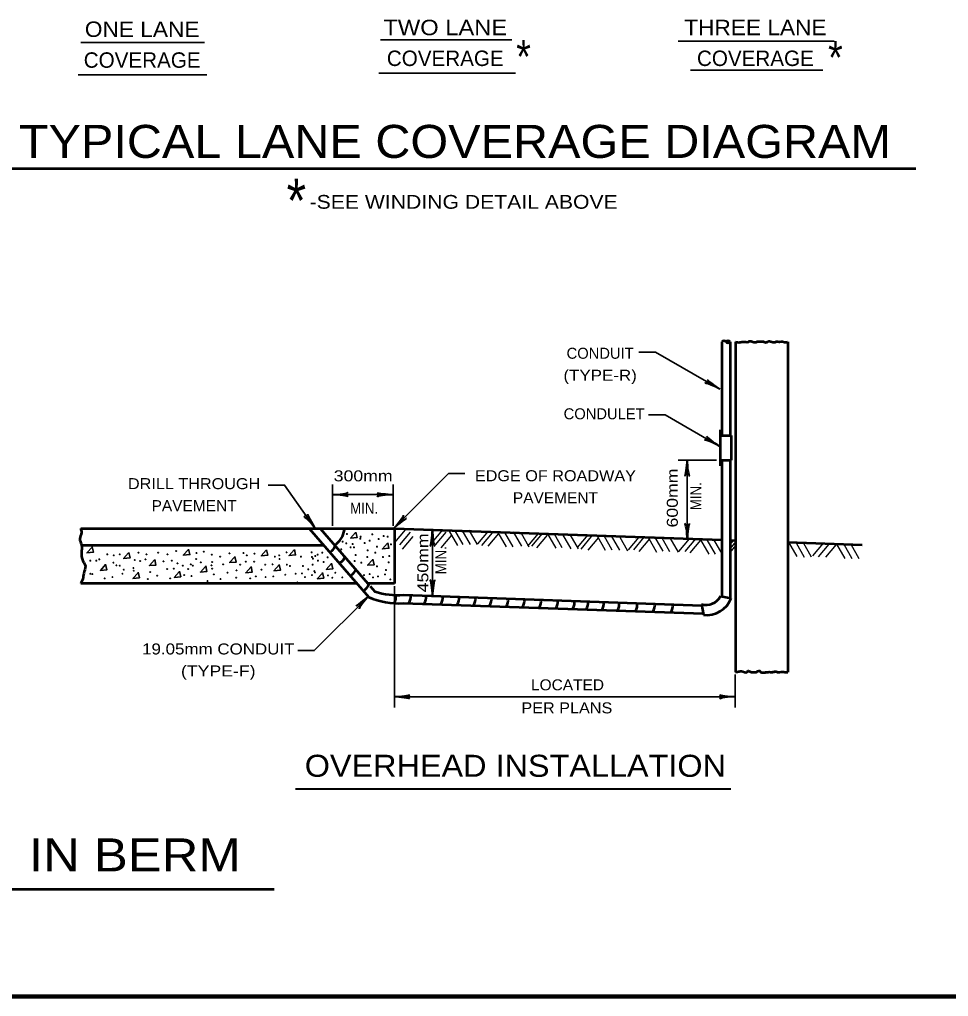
# Model space of a CAD drawing. Extents: x -90 to 623, y -379 to 75.
# Drawn here: x 208.1 to 376.8, y -369 to -191.5 of the extents above; entities that cross this region are included whole.
import ezdxf
from ezdxf.enums import TextEntityAlignment as Align

# ---------------------------------------------------------------- set-up
doc = ezdxf.new("R2010")
doc.units = 0
doc.header["$LTSCALE"] = 0.8
doc.layers.add('1', color=7, linetype='Continuous', lineweight=35)

msp = doc.modelspace()

# ---------------------------------------------------------------- linework, layer by layer
at = {"layer": '1'}
for p, q in [((273.6443, -195.1968), (297.5145, -195.1968)), ((219.2203, -195.6742), (241.6589, -195.6742)), ((327.7501, -195.4353), (356.0764, -195.4353)), ((218.7429, -201.5622), (242.1358, -201.5622)), ((273.3261, -201.2439), (298.1557, -201.2439)), ((329.9779, -200.6867), (354.0093, -200.6867)), ((334.7117, -271.5813), (327.7117, -271.5813)), ((329.3632, -271.5813), (329.3632, -285.9298)), ((264.9297, -283.5143), (264.9297, -276.0143)), ((275.9297, -283.5143), (275.9297, -276.0143)), ((264.9297, -277.8252), (275.9297, -277.8252)), ((283.0888, -284.2984), (283.0888, -296.1737)), ((276.1878, -294.4728), (276.1878, -316.4728)), ((338.0836, -310.4742), (338.0836, -316.4728)), ((276.1108, -314.5437), (338.084, -314.5437))]:
    msp.add_line(p, q, dxfattribs=at)
at = {"layer": '1', "lineweight": 53}
for p, q in [((204.4208, -218.5891), (370.8755, -218.5891)), ((335.6542, -250.0603), (335.6542, -267.0735)), ((337.1542, -250.0603), (337.1542, -267.0444)), ((338.1542, -250.0603), (338.1542, -310.0603)), ((347.6542, -250.0603), (347.6542, -310.0603)), ((335.3657, -266.0735), (335.3657, -272.5735)), ((335.3657, -267.0735), (337.3657, -267.0735)), ((337.3657, -267.0735), (337.3657, -271.5735)), ((335.3657, -271.5735), (336.1215, -271.5735)), ((335.6542, -271.6081), (335.6542, -296.3446)), ((260.7029, -283.9838), (271.5212, -296.4288)), ((262.6904, -283.9838), (271.3629, -293.9603)), ((276.1904, -283.9838), (335.6577, -286.0605)), ((219.1904, -286.9838), (263.3107, -286.9838)), ((337.1684, -286.1132), (338.1427, -286.1472)), ((347.6183, -286.4781), (361.1402, -286.9502)), ((269.264, -293.9838), (219.1904, -293.9838)), ((276.1904, -293.9838), (271.3599, -293.9838)), ((271.8045, -294.4684), (272.6533, -295.4447)), ((277.8081, -296.0476), (332.0119, -297.9405)), ((335.4013, -296.3), (337.3707, -296.6472)), ((277.7557, -297.5467), (332.2782, -299.4507)), ((331.9733, -297.7213), (332.3205, -299.6909)), ((122.0016, -349.4891), (254.329, -349.4891))]:
    msp.add_line(p, q, dxfattribs=at)
at = {"layer": '1', "lineweight": 25}
for p, q in [((278.1212, -284.214), (276.1928, -286.5123)), ((279.0133, -284.6195), (277.085, -286.9178)), ((279.5, -285.4306), (277.5717, -287.7289)), ((284.9343, -284.214), (283.006, -286.5123)), ((285.5021, -284.6195), (283.5738, -286.9178)), ((286.5565, -285.1873), (284.6282, -287.4856)), ((286.1406, -284.4443), (287.6406, -287.0424)), ((287.1139, -284.2821), (288.6139, -286.8802)), ((288.4117, -284.2821), (289.9117, -286.8802)), ((289.7094, -284.2821), (291.2094, -286.8802)), ((293.2074, -284.4573), (291.2791, -286.7557)), ((293.9374, -284.7817), (292.0091, -287.0801)), ((295.0729, -284.8628), (293.1446, -287.1612)), ((294.9815, -284.6877), (296.4815, -287.2858)), ((296.1982, -284.6877), (297.6982, -287.2858)), ((297.7392, -284.6065), (299.2392, -287.2046)), ((299.1181, -284.6877), (300.6181, -287.2858)), ((302.2917, -284.8628), (300.3633, -287.1612)), ((303.0217, -284.8628), (301.0933, -287.1612)), ((303.9138, -285.1873), (301.9855, -287.4856)), ((303.9846, -284.9309), (305.4846, -287.529)), ((305.1202, -284.8498), (306.6202, -287.4479)), ((306.7423, -285.0932), (308.2423, -287.6912)), ((308.0401, -285.0932), (309.5401, -287.6912)), ((311.2947, -285.1062), (309.3664, -287.4045)), ((311.9437, -285.4306), (310.0153, -287.7289)), ((313.2414, -285.5928), (311.3131, -287.8912)), ((312.9878, -285.3365), (314.4878, -287.9346)), ((314.2043, -285.2554), (315.7043, -287.8535)), ((315.5832, -285.3365), (317.0832, -287.9346)), ((317.0432, -285.4176), (318.5432, -288.0157)), ((320.5817, -285.5523), (318.6534, -287.8506)), ((321.5145, -285.5523), (319.5862, -287.8506)), ((322.3152, -285.6609), (323.8152, -288.259)), ((323.4507, -285.4987), (324.9507, -288.0968)), ((324.6674, -285.5798), (326.1674, -288.1779)), ((326.2085, -285.6609), (327.7085, -288.259)), ((322.5283, -285.8362), (320.6, -288.1345)), ((329.7065, -285.8767), (327.7782, -288.175)), ((330.8826, -285.8767), (328.9543, -288.175)), ((331.7748, -286.0795), (329.8465, -288.3778)), ((331.805, -286.0665), (333.305, -288.6646)), ((332.9406, -286.0665), (334.4406, -288.6646)), ((334.1572, -285.9854), (335.6572, -288.5835)), ((337.7128, -286.1322), (337.1542, -286.7982)), ((338.1542, -286.4056), (337.1542, -287.5974)), ((338.1542, -287.0597), (337.1542, -288.2515)), ((347.7923, -286.4734), (349.2923, -289.0715)), ((349.1294, -286.5897), (350.6294, -289.1877)), ((350.4084, -286.5316), (351.9084, -289.1297)), ((354.0408, -286.6608), (352.1125, -288.9592)), ((355.0872, -286.8352), (353.1589, -289.1336)), ((356.4243, -286.8934), (354.496, -289.1918)), ((356.5127, -286.8222), (358.0127, -289.4203)), ((357.7917, -286.8222), (359.2917, -289.4203)), ((359.0707, -286.8222), (360.5707, -289.4203))]:
    msp.add_line(p, q, dxfattribs=at)
at = {"layer": '1', "lineweight": 40}
msp.add_line((258.2395, -331.2874), (337.3024, -331.2874), dxfattribs=at)
at = {"layer": '1', "lineweight": 158}
msp.add_line((617.1938, -368.9978), (-42.4728, -368.9978), dxfattribs=at)
at = {"layer": '1'}
for points in [[(335.2931, -258.6751), (323.6017, -251.9251), (320.6017, -251.9251)], [(335.1887, -269.0025), (325.3458, -263.3197), (322.3458, -263.3197)], [(276.0824, -283.9095), (285.9819, -274.01), (288.9819, -274.01)], [(261.7322, -283.9311), (256.2447, -276.094), (253.2447, -276.094)], [(269.1261, -284.694), (268.2047, -285.7305), (269.3947, -285.6153), (269.1644, -284.6173)], [(221.2519, -287.3774), (220.3306, -288.4139), (221.5206, -288.2987), (221.2902, -287.3007)], [(274.9197, -286.6456), (273.9984, -287.6821), (275.1884, -287.5669), (274.9581, -286.5688)], [(227.8994, -288.4142), (226.9781, -289.4507), (228.1681, -289.3355), (227.9377, -288.3374)], [(238.755, -287.8043), (237.8337, -288.8408), (239.0237, -288.7257), (238.7933, -287.7276)], [(247.1711, -289.146), (246.2498, -290.1825), (247.4398, -290.0673), (247.2094, -289.0693)], [(252.9038, -287.9262), (251.9824, -288.9627), (253.1724, -288.8476), (252.9421, -287.8495)], [(257.9656, -287.8653), (257.0442, -288.9018), (258.2342, -288.7867), (258.0039, -287.7886)], [(223.6914, -290.5487), (222.7701, -291.5852), (223.9601, -291.47), (223.7297, -290.4719)], [(232.5953, -289.6949), (231.674, -290.7314), (232.864, -290.6162), (232.6337, -289.6182)], [(241.8653, -290.8536), (240.9439, -291.8901), (242.1339, -291.7749), (241.9036, -290.7768)], [(250.0984, -290.9756), (249.1771, -292.0121), (250.3671, -291.8969), (250.1367, -290.8988)], [(255.2212, -290.6097), (254.2999, -291.6462), (255.4899, -291.531), (255.2596, -290.5329)], [(264.7351, -290.3657), (263.8137, -291.4022), (265.0037, -291.2871), (264.7734, -290.289)], [(272.2363, -289.6339), (271.315, -290.6704), (272.505, -290.5553), (272.2747, -289.5572)], [(229.607, -292.0123), (228.6857, -293.0488), (229.8757, -292.9337), (229.6453, -291.9356)], [(237.1083, -291.8294), (236.187, -292.8659), (237.377, -292.7507), (237.1467, -291.7527)], [(263.0884, -292.0733), (262.1671, -293.1098), (263.3571, -292.9947), (263.1268, -291.9966)], [(271.5311, -296.2456), (261.6316, -306.1451), (258.6316, -306.1451)]]:
    msp.add_lwpolyline(points, dxfattribs=at)
at = {"layer": '1', "lineweight": 53}
for points in [[(336.1215, -271.5735), (337.1098, -271.5735), (337.3657, -271.5735)], [(337.1542, -271.6081), (337.1542, -286.1272), (337.1542, -296.6091)], [(219.1904, -283.9838), (276.1904, -283.9838), (276.1904, -293.9838)]]:
    msp.add_lwpolyline(points, dxfattribs=at)
at = {"layer": '1'}
for centre in [(267.5679, -284.9851), (270.0532, -285.47), (272.1747, -285.0457), (274.2357, -285.3487), (274.963, -285.47), (266.7799, -286.3793), (267.4467, -286.6823), (268.2347, -287.4097), (268.5983, -286.8036), (268.8408, -287.4097), (269.9925, -285.8338), (270.7805, -286.6217), (271.6898, -286.1974), (273.0233, -287.2885), (273.3264, -285.8943), (275.5692, -286.8642), (224.0457, -288.6827), (225.1975, -288.8645), (226.2886, -288.6827), (229.6831, -288.3796), (231.1378, -288.6827), (233.2594, -288.3796), (234.9566, -288.6827), (236.5327, -288.0765), (240.2302, -288.4402), (241.5637, -288.1977), (243.0185, -288.7432), (244.5339, -289.107), (246.2312, -288.5008), (248.777, -288.4402), (249.3832, -288.8645), (250.7773, -288.5614), (254.4749, -289.107), (255.2629, -288.8645), (256.5964, -288.3189), (259.2029, -289.107), (261.1427, -288.3189), (261.2032, -289.1676), (261.8094, -288.9857), (262.2337, -288.7432), (263.0823, -288.3796), (264.0522, -289.2282), (266.5374, -287.7734), (269.1439, -288.8039), (271.2654, -289.1676), (271.3261, -287.9552), (272.7202, -288.3796), (274.1144, -289.1676), (275.2661, -288.9857), (220.9544, -289.8343), (222.0455, -289.8343), (222.591, -289.5919), (225.1368, -290.1981), (225.6824, -290.683), (226.2886, -290.7436), (229.0162, -289.7131), (229.9862, -289.895), (230.956, -289.5919), (234.2292, -289.9556), (235.7447, -289.8343), (236.7751, -290.3193), (237.7449, -290.7436), (239.1997, -290.5011), (239.5634, -290.7436), (240.1696, -289.5312), (241.0182, -290.1374), (242.9579, -290.683), (243.0792, -290.0768), (245.0794, -290.5011), (248.1708, -290.5618), (249.2013, -290.0162), (250.7167, -290.0162), (252.717, -290.5618), (254.0506, -290.5011), (255.3235, -289.5312), (256.6571, -290.5618), (257.2026, -290.8042), (259.5666, -290.8042), (261.3245, -290.5618), (261.3851, -289.4707), (262.2943, -289.8343), (263.3248, -290.0768), (268.9621, -289.895), (270.1743, -290.1981), (273.0233, -290.8648), (275.1448, -290.1374), (220.9544, -292.1983), (221.3181, -292.259), (224.955, -292.8045), (226.7735, -292.1983), (227.016, -291.471), (228.7738, -291.1679), (228.8344, -291.6528), (231.8046, -291.8952), (233.0775, -292.5621), (234.896, -291.3497), (236.1083, -291.2892), (237.9874, -292.4408), (238.7148, -291.3497), (239.3209, -292.6227), (243.0792, -291.2892), (243.3822, -292.3196), (245.8674, -292.0165), (247.5041, -291.5922), (251.0198, -292.6832), (252.0503, -291.471), (252.7777, -292.8045), (254.1718, -292.6832), (256.354, -292.3802), (258.2331, -292.1983), (259.3847, -292.1377), (259.9303, -292.8045), (260.5365, -291.4103), (261.2032, -292.4408), (261.6276, -291.7134), (261.7487, -291.9559), (264.1128, -292.5014), (265.4463, -292.0165), (266.7192, -292.8652), (266.9617, -291.1679), (270.6593, -292.4408), (271.6898, -292.259), (272.2959, -292.8652), (273.2052, -292.6832), (274.4781, -292.3196), (274.6599, -291.5316), (223.5608, -293.047), (231.3803, -293.1683), (235.4416, -293.047), (242.2305, -293.5319), (244.5945, -293.1683), (247.4435, -292.9257), (249.9893, -293.047), (258.5362, -293.7743), (264.9008, -292.9257), (275.4479, -293.2288)]:
    msp.add_circle(centre, 0.0607, dxfattribs=at)
at = {"layer": '1', "lineweight": 53}
for centre, radius, start, end in [((336.0292, -250.4071), 0.4965, 40.95184, 139.04816), ((336.7735, -249.732), 0.4984, 221.20556, 318.79444), ((336.7792, -250.4273), 0.5247, 44.37838, 135.62162), ((263.3525, -283.756), 3.7689, 301.08152, 353.13064), ((263.4115, -286.3695), 2.1707, 299.00343, 339.84739), ((265.208, -288.3457), 2.1707, 299.00343, 339.84739), ((267.1841, -290.6213), 2.1707, 299.00343, 339.84739), ((269.5196, -293.3759), 2.1707, 299.00343, 339.84739), ((276.7774, -282.5203), 13.5665, 252.30241, 274.35724), ((274.296, -296.3416), 2.1707, 327.00343, 7.84739), ((276.9908, -296.3416), 2.1707, 327.00343, 7.84739), ((279.7753, -296.4913), 2.1707, 327.00343, 7.84739), ((282.7995, -296.5212), 2.1707, 327.00343, 7.84739), ((285.7638, -296.641), 2.1707, 327.00343, 7.84739), ((332.8255, -294.9323), 2.9163, 253.00765, 332.03255), ((276.8528, -284.6377), 12.9405, 245.66897, 274.00127), ((288.728, -296.7608), 2.1707, 327.00343, 7.84739), ((291.6324, -296.8506), 2.1707, 327.00343, 7.84739), ((294.6565, -297.0004), 2.1707, 327.00343, 7.84739), ((297.6208, -297.0902), 2.1707, 327.00343, 7.84739), ((300.6449, -297.18), 2.1707, 327.00343, 7.84739), ((303.699, -297.3297), 2.1707, 327.00343, 7.84739), ((306.7531, -297.3297), 2.1707, 327.00343, 7.84739), ((309.2083, -297.5094), 2.1707, 327.00343, 7.84739), ((312.0528, -297.5992), 2.1707, 327.00343, 7.84739), ((314.8673, -297.689), 2.1707, 327.00343, 7.84739), ((318.131, -297.8088), 2.1707, 327.00343, 7.84739), ((321.3048, -297.9285), 2.1707, 327.00343, 7.84739), ((324.5685, -298.0184), 2.1707, 327.00343, 7.84739), ((332.8325, -294.8288), 4.889, 263.98872, 338.16404)]:
    msp.add_arc(centre, radius, start, end, dxfattribs=at)
at = {"layer": '1', "lineweight": 40}
for centre, major_axis, ratio, start_param, end_param in [((334.4285, -257.9316), (-1.4333, 1.0303), 0.07063, 6.28230741, 8.55970261), ((334.4285, -257.9316), (-1.4333, 1.0303), 0.07063, 6.28230741, 8.55970261), ((334.2099, -258.3688), (1.6245, -0.7576), 0.122415, 0.89635335, 3.14159265), ((334.2099, -258.3688), (1.6245, -0.7576), 0.122415, 0.89635335, 3.14159265), ((334.1055, -268.6962), (1.6245, -0.7576), 0.122415, 0.89635335, 3.14159265), ((334.1055, -268.6962), (1.6245, -0.7576), 0.122415, 0.89635335, 3.14159265), ((334.3241, -268.259), (1.4333, -1.0303), 0.07063, 3.14071475, 5.41810995), ((334.3241, -268.259), (1.4333, -1.0303), 0.07063, 3.14071475, 5.41810995), ((329.1516, -272.7018), (-0.1757, -1.7565), 0.07063, 6.28230741, 8.55970261), ((329.1516, -272.7018), (-0.1757, -1.7565), 0.07063, 6.28230741, 8.55970261), ((329.6395, -272.6724), (-0.1562, 1.7857), 0.122415, 0.89635335, 3.14159265), ((329.6395, -272.6724), (-0.1562, 1.7857), 0.122415, 0.89635335, 3.14159265), ((266.0502, -278.0369), (1.7565, -0.1757), 0.07063, 6.28230741, 8.55970261), ((266.0502, -278.0369), (1.7565, -0.1757), 0.07063, 6.28230741, 8.55970261), ((266.0209, -277.549), (-1.7857, -0.1562), 0.122415, 0.89635335, 3.14159265), ((266.0209, -277.549), (-1.7857, -0.1562), 0.122415, 0.89635335, 3.14159265), ((274.8385, -278.1015), (1.7857, 0.1562), 0.122415, 0.89635335, 3.14159265), ((274.8385, -278.1015), (1.7857, 0.1562), 0.122415, 0.89635335, 3.14159265), ((274.8092, -277.6136), (1.7565, -0.1757), 0.07063, 3.14071475, 5.41810995), ((274.8092, -277.6136), (1.7565, -0.1757), 0.07063, 3.14071475, 5.41810995), ((260.88, -283.1957), (1.1521, -1.3732), 0.122415, 0.89635335, 3.14159265), ((261.2628, -282.8919), (-0.8636, 1.5396), 0.07063, 6.28230741, 8.55970261), ((276.6586, -282.9425), (-1.1523, -1.3731), 0.122415, 0.89635335, 3.14159265), ((276.6586, -282.9425), (-1.1523, -1.3731), 0.122415, 0.89635335, 3.14159265), ((277.0244, -283.2668), (1.3662, 1.1178), 0.07063, 6.28230741, 8.55970261), ((277.0244, -283.2668), (1.3662, 1.1178), 0.07063, 6.28230741, 8.55970261), ((329.0869, -284.8386), (0.1562, -1.7857), 0.122415, 0.89635335, 3.14159265), ((329.0869, -284.8386), (0.1562, -1.7857), 0.122415, 0.89635335, 3.14159265), ((329.5748, -284.8093), (0.1757, 1.7565), 0.07063, 6.28230741, 8.55970261), ((329.5748, -284.8093), (0.1757, 1.7565), 0.07063, 6.28230741, 8.55970261), ((282.8772, -285.4189), (-0.1757, -1.7565), 0.07063, 6.28230741, 8.55970261), ((282.8772, -285.4189), (-0.1757, -1.7565), 0.07063, 6.28230741, 8.55970261), ((283.3651, -285.3896), (-0.1562, 1.7857), 0.122415, 0.89635335, 3.14159265), ((283.3651, -285.3896), (-0.1562, 1.7857), 0.122415, 0.89635335, 3.14159265), ((282.8125, -295.0826), (0.1562, -1.7857), 0.122415, 0.89635335, 3.14159265), ((282.8125, -295.0826), (0.1562, -1.7857), 0.122415, 0.89635335, 3.14159265), ((283.3004, -295.0532), (0.1757, 1.7565), 0.07063, 6.28230741, 8.55970261), ((283.3004, -295.0532), (0.1757, 1.7565), 0.07063, 6.28230741, 8.55970261), ((270.5891, -296.8883), (1.3662, 1.1178), 0.07063, 3.14071475, 5.41810995), ((270.9549, -297.2126), (1.1523, 1.3731), 0.122415, 0.89635335, 3.14159265), ((277.202, -314.2674), (-1.7857, -0.1562), 0.122415, 0.89635335, 3.14159265), ((277.2313, -314.7553), (1.7565, -0.1757), 0.07063, 6.28230741, 8.55970261), ((336.9928, -314.82), (1.7857, 0.1562), 0.122415, 0.89635335, 3.14159265), ((336.9635, -314.3321), (1.7565, -0.1757), 0.07063, 3.14071475, 5.41810995)]:
    msp.add_ellipse(centre, major_axis=major_axis, ratio=ratio, start_param=start_param, end_param=end_param, dxfattribs=at)
at = {"layer": '1', "lineweight": 53}
for points in [[(338.1542, -250.0603), (338.906, -250.153), (339.2802, -250.0632), (340.0138, -250.0931), (340.4778, -250.0931), (340.6874, -249.9584), (341.2862, -250.0482), (341.9, -250.1231), (342.1396, -250.0182), (342.7533, -250.0332), (343.1874, -250.0182), (343.4419, -250.138), (343.936, -250.0482), (344.0408, -249.9883), (344.4001, -249.9584), (344.5797, -250.0032), (344.924, -250.1231), (345.4779, -250.0632), (345.6576, -250.0032), (345.9569, -250.0182), (346.1542, -250.0603)], [(346.1542, -250.0603), (346.6732, -249.9902), (347.0365, -250.1355), (347.6542, -250.0603)], [(219.1904, -283.9838), (219.3292, -284.7203), (219.0297, -285.8581), (219.3292, -286.8762), (219.3891, -287.6546), (219.4489, -289.511), (220.0477, -290.8284), (219.7483, -292.1458), (219.5687, -293.104), (219.1904, -293.9838)], [(338.1542, -310.0603), (338.7937, -309.956), (339.2428, -309.9111), (340.1859, -310.0757), (340.3656, -309.8812), (340.8446, -310.0159), (341.2338, -310.0608), (341.5931, -310.0608), (341.9374, -310.0608), (342.0572, -309.986), (342.641, -309.9111), (342.7608, -310.1058), (343.0602, -310.1507), (343.5093, -310.1357), (343.7937, -310.0757), (343.9285, -310.0757), (344.2728, -310.0308), (344.662, -310.1058), (345.0063, -310.0458), (345.171, -310.0159), (345.4105, -309.9411), (345.665, -310.0009), (345.9195, -310.0908), (346.1542, -310.0603)], [(346.1542, -310.0603), (346.6877, -310.0365), (347.0947, -310.0656), (347.6542, -310.0603)]]:
    msp.add_spline(points, degree=3, dxfattribs=at)

# ---------------------------------------------------------------- texts
at = {"layer": '1'}
for s, height, width, p in [('TWO LANE', 2.8, 1.15, (285.4203, -194.3538)), ('THREE LANE', 2.8, 1.1, (341.754, -194.3537)), ('ONE LANE', 2.8, 1.1, (230.3598, -194.6721)), ('TYPICAL LANE COVERAGE DIAGRAM', 6, 1.1, (287.1707, -216.6561)), ('*', 8, 0.85, (258.3675, -228.3973)), ('-SEE WINDING DETAIL ABOVE', 2.5, 1.15, (288.7621, -225.8862)), ('(TYPE-R)', 2, 1.15, (313.5504, -257.1405)), ('DRILL THROUGH', 2, 1.1, (239.7929, -276.8308)), ('EDGE OF ROADWAY', 2, 1.1, (305.4257, -275.3937)), ('PAVEMENT', 2, 1.05, (305.4257, -279.3937)), ('PAVEMENT', 2, 1.05, (239.7929, -280.8308)), ('19.05mm CONDUIT', 2, 1.15, (244.1888, -306.8643)), ('(TYPE-F)', 2, 1.2, (244.1888, -310.8643))]:
    msp.add_text(s, height=height, dxfattribs=dict(at, width=width)).set_placement(p, align=Align.CENTER)
for s, height, width, p in [('*', 6, 0.85, (298.31, -201.2437)), ('*', 6, 0.85, (354.962, -201.4027)), ('300mm', 2, 1.2, (265.1552, -275.4141)), ('MIN.', 2, 0.9, (268.1284, -281.2972)), ('LOCATED', 2, 1.05, (300.9929, -313.3809)), ('PER PLANS', 2, 1.1, (299.2489, -317.5668)), ('OVERHEAD INSTALLATION', 4, 1.1, (259.8941, -329.0888)), ('TYPICAL SECTION IN BERM', 6, 1.15, (125.2095, -346.2812))]:
    msp.add_text(s, height=height, dxfattribs=dict(at, width=width)).set_placement(p)
for s, height, p in [('COVERAGE', 2.8, (230.3598, -200.2721)), ('COVERAGE', 2.8, (285.4203, -199.9538)), ('COVERAGE', 2.8, (341.754, -199.9537)), ('CONDUIT', 2, (313.5504, -253.1405))]:
    msp.add_text(s, height=height, dxfattribs=at).set_placement(p, align=Align.CENTER)
msp.add_text('CONDULET', height=2, dxfattribs=at).set_placement((306.9228, -264.1398))
for s, width, p in [('600mm', 1.2, (327.6615, -283.79)), ('MIN.', 0.9, (331.9212, -280.6505)), ('450mm', 1.2, (282.3422, -295.571)), ('MIN.', 0.9, (285.6041, -292.2921))]:
    msp.add_text(s, height=2, rotation=90, dxfattribs=dict(at, width=width)).set_placement(p)

doc.saveas('drawing.dxf')
